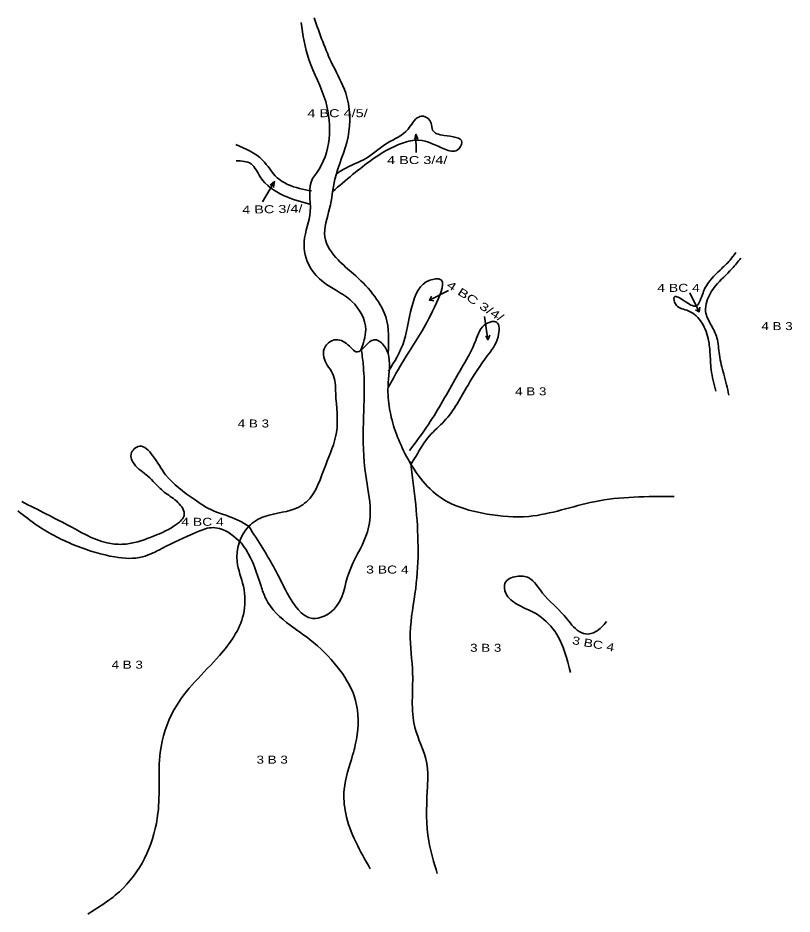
# Model space of a CAD drawing. Extents: x -509878 to -506977, y -1124122 to -1120763.
import ezdxf
from ezdxf.enums import TextEntityAlignment as Align

# ---------------------------------------------------------------- set-up
doc = ezdxf.new("R2010")
doc.units = 0
doc.header["$LTSCALE"] = 12
doc.layers.add('10', color=7, linetype='Continuous', lineweight=35)

msp = doc.modelspace()

# ---------------------------------------------------------------- linework, layer by layer
at = {"layer": '10'}
for p, q in [((-508386.15, -1121199.01), (-508384.97, -1121267.19)), ((-508916.96, -1121376.52), (-508961.68, -1121451.75)), ((-508264.92, -1121784.42), (-508335.54, -1121820.86)), ((-507359.8, -1121793.37), (-507324.49, -1121863.9)), ((-508129.57, -1121881.99), (-508116.62, -1121968.98))]:
    msp.add_line(p, q, dxfattribs=at)
for points in [[(-508390.86, -1121217.82), (-508386.15, -1121199.01), (-508379.09, -1121215.47)], [(-508932.26, -1121389.45), (-508916.96, -1121376.52), (-508920.49, -1121398.85)], [(-508328.48, -1121805.58), (-508335.54, -1121820.86), (-508319.06, -1121823.21)], [(-507322.14, -1121847.45), (-507324.49, -1121863.9), (-507338.61, -1121856.85)], [(-508109.56, -1121951.35), (-508116.62, -1121968.98), (-508124.86, -1121954.87)]]:
    msp.add_lwpolyline(points, dxfattribs=at)
for points in [[(-508767.76, -1120762.68), (-508698.57, -1120938.33), (-508649.55, -1121044.87), (-508640.9, -1121209), (-508689.92, -1121367.38), (-508710.1, -1121476.8), (-508727.4, -1121583.34), (-508678.38, -1121669.73), (-508620.72, -1121721.56), (-508548.65, -1121796.43), (-508499.63, -1121882.81), (-508490.15, -1122019.49)], [(-508592.37, -1122007.19), (-508574.59, -1121931.76), (-508626.49, -1121825.22), (-508684.15, -1121784.91), (-508733.16, -1121753.23), (-508782.17, -1121698.52), (-508805.24, -1121600.62), (-508782.17, -1121488.32), (-508773.53, -1121364.5), (-508759.11, -1121344.34), (-508724.51, -1121076.55), (-508787.94, -1120918.17), (-508816.77, -1120779.96)], [(-508698.56, -1121413.45), (-508623.61, -1121350.1), (-508548.65, -1121292.51), (-508436.21, -1121232.04), (-508375.66, -1121220.52), (-508277.64, -1121255.08), (-508231.51, -1121257.96), (-508214.21, -1121229.16), (-508280.52, -1121203.25), (-508323.77, -1121183.09), (-508329.53, -1121157.17), (-508358.36, -1121131.26), (-508375.66, -1121134.14), (-508416.03, -1121180.21), (-508493.87, -1121232.04), (-508574.59, -1121289.63), (-508646.67, -1121324.19), (-508685.43, -1121347.64)], [(-509061.83, -1121237.8), (-508960.92, -1121295.39), (-508906.15, -1121361.62), (-508822.54, -1121401.93), (-508778.09, -1121411.14)], [(-508779.67, -1121462.06), (-508883.08, -1121427.85), (-508969.57, -1121358.74), (-509004.17, -1121309.79), (-509060.35, -1121298.01)], [(-507263.03, -1122162.08), (-507279.8, -1122081.83), (-507284.5, -1122016), (-507291.57, -1121964.28), (-507319.81, -1121898.45), (-507371.6, -1121858.48), (-507413.97, -1121834.97), (-507418.68, -1121809.11), (-507381.02, -1121823.21), (-507336.29, -1121842.02), (-507310.4, -1121792.65), (-507303.34, -1121776.19), (-507246.84, -1121708.01), (-507209.18, -1121670.4), (-507187.99, -1121642.18)], [(-507169.16, -1121663.34), (-507202.12, -1121703.31), (-507263.32, -1121766.79), (-507296.27, -1121825.56), (-507300.98, -1121863.18), (-507279.8, -1121914.91), (-507258.61, -1121961.93), (-507249.2, -1122025.4), (-507232.72, -1122098.29), (-507213.49, -1122177.08)], [(-508489.19, -1122086.33), (-508430.44, -1121972.08), (-508318, -1121741.72), (-508297.82, -1121741.72), (-508309.35, -1121830.98), (-508413.14, -1122015.27), (-508490.91, -1122147.73)], [(-508410.26, -1122383.85), (-508346.83, -1122297.46), (-508240.16, -1122118.93), (-508191.15, -1122032.55), (-508162.32, -1121972.08), (-508121.95, -1121908.73), (-508084.47, -1121902.97), (-508078.71, -1121957.68), (-508119.07, -1122029.67), (-508191.15, -1122139.09), (-508280.52, -1122274.43), (-508335.3, -1122329.14), (-508387.2, -1122406.89), (-508405.69, -1122436.18)], [(-507418.53, -1122556.29), (-507718.36, -1122576.45), (-507963.42, -1122631.16), (-508119.11, -1122622.52), (-508292.09, -1122562.05), (-508427.6, -1122395.04), (-508485.26, -1122228.03), (-508491.03, -1122144.52), (-508488.14, -1122032.22), (-508508.32, -1121989.03), (-508542.92, -1121968.87), (-508606.35, -1122014.95), (-508646.71, -1121983.27), (-508698.61, -1121971.75), (-508730.32, -1122003.43), (-508718.79, -1122063.9), (-508698.61, -1122095.57), (-508687.07, -1122170.44), (-508684.19, -1122317.29), (-508724.55, -1122438.24), (-508796.63, -1122576.45), (-508825.46, -1122596.61), (-508952.32, -1122631.16), (-509012.86, -1122668.6), (-509056.11, -1122801.05), (-509033.04, -1122893.2), (-509033.04, -1122999.74), (-509122.42, -1123152.36), (-509292.52, -1123355.07), (-509344.41, -1123516.33), (-509353.06, -1123743.81), (-509482.8, -1124024.28), (-509615.42, -1124122.18)], [(-509012.83, -1122668.55), (-508914.84, -1122829.27), (-508868.71, -1122918.54), (-508773.57, -1123013.56), (-508692.84, -1122979.01), (-508638.06, -1122843.67), (-508571.75, -1122699.7), (-508557.34, -1122610.43), (-508574.63, -1122477.97), (-508583.28, -1122279.28), (-508583.28, -1122069.08), (-508590.13, -1122009.77)], [(-509863.36, -1122575.88), (-509678.85, -1122670.9), (-509523.16, -1122734.25), (-509465.5, -1122734.25), (-509370.36, -1122705.45), (-509280.98, -1122659.38), (-509255.04, -1122627.71), (-509278.1, -1122578.76), (-509324.23, -1122544.2), (-509364.59, -1122506.77), (-509390.54, -1122480.85), (-509442.44, -1122434.78), (-509453.97, -1122397.34), (-509422.26, -1122368.55), (-509373.24, -1122403.1), (-509324.23, -1122475.09), (-509217.56, -1122567.24), (-509145.48, -1122610.43), (-509053.22, -1122644.98), (-509012.57, -1122668.97)], [(-508306.51, -1123969.56), (-508338.22, -1123848.62), (-508343.99, -1123661.46), (-508346.87, -1123552.03), (-508390.12, -1123422.46), (-508398.77, -1123220.89), (-508407.42, -1123068.27), (-508387.23, -1122901.26), (-508387.23, -1122587.39), (-508406.97, -1122425.68)], [(-509042.46, -1122729.82), (-509122.42, -1122676.66), (-509154.13, -1122673.78), (-509208.91, -1122691.06), (-509338.65, -1122751.53), (-509410.72, -1122783.2), (-509514.51, -1122783.2), (-509655.78, -1122742.89), (-509805.7, -1122665.14), (-509877.78, -1122610.43)], [(-508557.34, -1123952.29), (-508649.59, -1123744.96), (-508655.36, -1123655.7), (-508623.65, -1123526.12), (-508606.35, -1123448.37), (-508617.88, -1123304.4), (-508681.31, -1123194.97), (-508782.22, -1123094.19), (-508857.17, -1123039.48), (-508949.43, -1122938.7), (-508966.73, -1122892.62), (-509024.39, -1122754.41), (-509045.92, -1122725.11)], [(-507807.7, -1123216.03), (-507859.59, -1123072.06), (-507925.9, -1123002.95), (-508003.75, -1122962.63), (-508049.88, -1122919.44), (-508052.76, -1122882.01), (-508009.51, -1122856.09), (-507963.38, -1122861.85), (-507911.49, -1122919.44), (-507830.76, -1123002.95), (-507781.75, -1123057.66), (-507750.04, -1123072.06), (-507712.56, -1123063.42), (-507672.2, -1123025.98)]]:
    msp.add_spline(points, degree=3, dxfattribs=at)

# ---------------------------------------------------------------- texts
for s, width, p in [('4 BC 4/5/ ', 1.35, (-508672.62, -1121134.74)), ('4 BC 4', 1.3, (-507402.17, -1121789.56)), ('4 B 3', 1.25, (-507033.25, -1121932.97)), ('4 B 3', 1.25, (-507956, -1122177.47)), ('4 B 3', 1.25, (-508995.52, -1122298.07)), ('4 BC 4', 1.3, (-509185.8, -1122666.65)), ('3 BC 4', 1.3, (-508493.07, -1122845.64)), ('3 B 3', 1.25, (-508124.84, -1123138.89)), ('4 B 3', 1.25, (-509468.34, -1123202.24)), ('3 B 3', 1.25, (-508925.17, -1123558.22))]:
    msp.add_text(s, height=30, dxfattribs=dict(at, width=width)).set_placement(p, align=Align.CENTER)
for s, rotation, width, p in [('4 BC 3/4/ ', 0.062, 1.35, (-508373.84, -1121310.44)), ('4 BC 3/4/ ', 1.107, 1.35, (-508916.64, -1121494.45)), ('4 BC 3/4/ ', 327.063, 1.45, (-508165.35, -1121841.18)), ('3 BC 4', 349.692, 1.3, (-507724.2, -1123123.97))]:
    msp.add_text(s, height=30, rotation=rotation, dxfattribs=dict(at, width=width)).set_placement(p, align=Align.CENTER)

doc.saveas('drawing.dxf')
